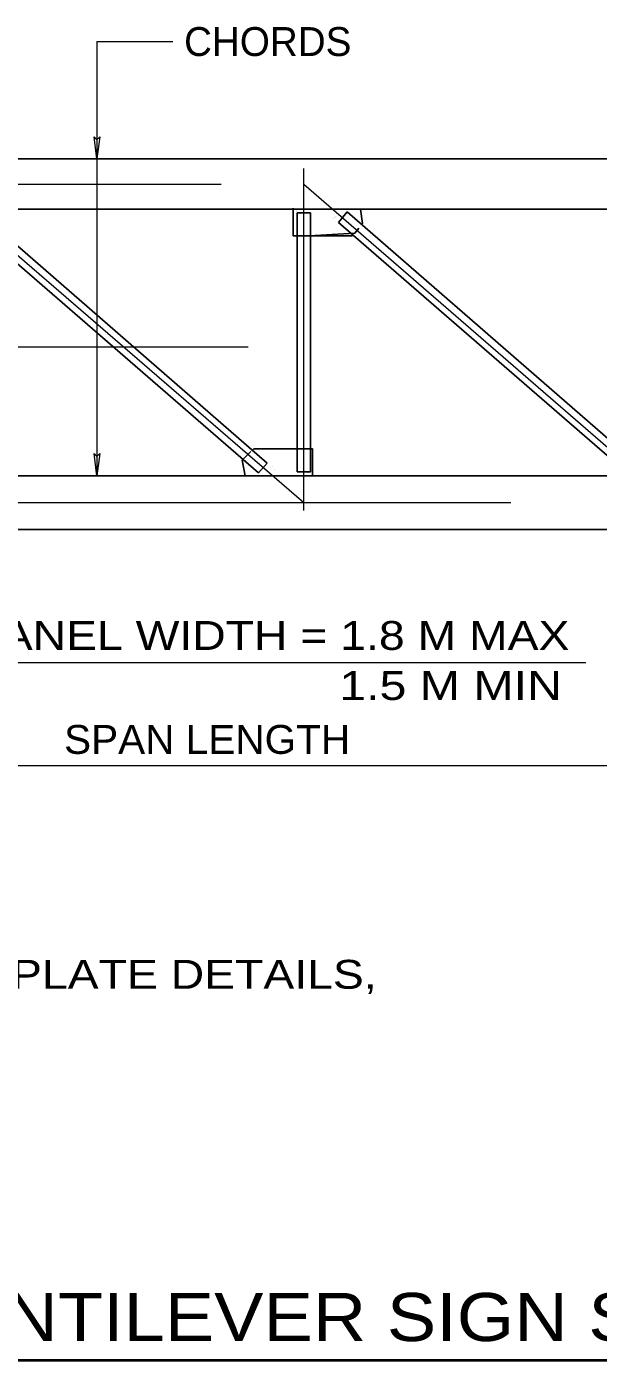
# Model space of a CAD drawing. Extents: x 312601.858 to 312602.699, y 144420.109 to 144420.704.
# Drawn here: x 312602.0731 to 312602.1325, y 144420.4937 to 144420.6322 of the extents above; entities that cross this region are included whole.
import ezdxf
from ezdxf.enums import TextEntityAlignment as Align

# ---------------------------------------------------------------- set-up
doc = ezdxf.new("R2010")
doc.units = 0
doc.header["$LTSCALE"] = 0.0012
doc.linetypes.add('DOT_DASHED', pattern=[7.7, 5, -1.2, 0.3, -1.2])
doc.layers.add('1', color=7, linetype='Continuous', lineweight=13)
doc.layers.add('2', color=7, linetype='Continuous', lineweight=25)

msp = doc.modelspace()

# ---------------------------------------------------------------- linework, layer by layer
at = {"layer": '1'}
for p, q in [((312602.0804, 144420.6307), (312602.0883, 144420.6307)), ((312602.0636, 144420.5662), (312602.1312, 144420.5662)), ((312602.0054, 144420.5555), (312602.1817, 144420.5555))]:
    msp.add_line(p, q, dxfattribs=at)
at = {"layer": '1', "lineweight": 25}
for p, q in [((312602.0222, 144420.6185), (312602.1817, 144420.6185)), ((312602.0677, 144420.6133), (312602.1012, 144420.6133)), ((312602.0682, 144420.6129), (312602.0981, 144420.5869)), ((312602.1008, 144420.6106), (312602.1008, 144420.6134)), ((312602.1008, 144420.6105), (312602.1008, 144420.6133)), ((312602.1008, 144420.6105), (312602.1008, 144420.6133)), ((312602.1008, 144420.6105), (312602.1008, 144420.6133)), ((312602.1008, 144420.6106), (312602.1008, 144420.6133)), ((312602.1012, 144420.586), (312602.1012, 144420.6129)), ((312602.1012, 144420.6129), (312602.1026, 144420.6129)), ((312602.1024, 144420.6133), (312602.1062, 144420.6133)), ((312602.1026, 144420.586), (312602.1026, 144420.6129)), ((312602.1064, 144420.613), (312602.1055, 144420.6119)), ((312602.106, 144420.6133), (312602.1394, 144420.6133)), ((312602.1064, 144420.613), (312602.1364, 144420.5869)), ((312602.0673, 144420.6118), (312602.0972, 144420.5859)), ((312602.1055, 144420.6119), (312602.1355, 144420.5859)), ((312602.108, 144420.6118), (312602.1079, 144420.6117)), ((312602.1008, 144420.6105), (312602.1012, 144420.6105)), ((312602.1008, 144420.6105), (312602.1012, 144420.6105)), ((312602.1008, 144420.6105), (312602.1012, 144420.6105)), ((312602.1069, 144420.6105), (312602.1025, 144420.6105)), ((312602.0966, 144420.5883), (312602.0967, 144420.5884)), ((312602.0967, 144420.5884), (312602.1011, 144420.5884)), ((312602.0967, 144420.5884), (312602.1011, 144420.5884)), ((312602.0967, 144420.5884), (312602.1011, 144420.5884)), ((312602.1028, 144420.5884), (312602.1024, 144420.5884)), ((312602.1028, 144420.5884), (312602.1024, 144420.5884)), ((312602.1028, 144420.5884), (312602.1024, 144420.5884)), ((312602.1028, 144420.5884), (312602.1028, 144420.5856)), ((312602.1028, 144420.5884), (312602.1028, 144420.5856)), ((312602.1028, 144420.5884), (312602.1028, 144420.5856)), ((312602.0972, 144420.5859), (312602.0981, 144420.5869)), ((312602.0643, 144420.5856), (312602.0976, 144420.5856)), ((312602.1012, 144420.5856), (312602.0974, 144420.5856)), ((312602.0988, 144420.5856), (312602.1009, 144420.5856)), ((312602.0991, 144420.5856), (312602.1012, 144420.5856)), ((312602.101, 144420.5856), (312602.0991, 144420.5856)), ((312602.1026, 144420.586), (312602.1012, 144420.586)), ((312602.1026, 144420.5856), (312602.1359, 144420.5856)), ((312602.0222, 144420.58), (312602.1817, 144420.58))]:
    msp.add_line(p, q, dxfattribs=at)
at = {"layer": '1', "linetype": 'DOT_DASHED'}
for p, q in [((312602.1019, 144420.582), (312602.1019, 144420.6175)), ((312601.9933, 144420.6159), (312602.1862, 144420.6159)), ((312602.0636, 144420.6159), (312602.1019, 144420.5828)), ((312602.1019, 144420.6159), (312602.1401, 144420.5828)), ((312601.9961, 144420.599), (312602.181, 144420.599))]:
    msp.add_line(p, q, dxfattribs=at)
at = {"layer": '1', "lineweight": 40}
msp.add_line((312601.9778, 144420.4937), (312602.169, 144420.4937), dxfattribs=at)
at = {"layer": '1'}
for points in [[(312602.0807, 144420.6208), (312602.0804, 144420.6185), (312602.0801, 144420.6208), (312602.0804, 144420.6205)], [(312602.0807, 144420.5879), (312602.0804, 144420.5856), (312602.0801, 144420.5879), (312602.0804, 144420.5876)]]:
    msp.add_lwpolyline(points, close=True, dxfattribs=at)
at = {"layer": '1', "lineweight": 25}
for points in [[(312602.1069, 144420.6105), (312602.1025, 144420.6105), (312602.1015, 144420.6105), (312602.1008, 144420.6105), (312602.1008, 144420.6133), (312602.1078, 144420.6133), (312602.108, 144420.6118)], [(312602.1076, 144420.6113), (312602.1072, 144420.6108), (312602.1025, 144420.6105)], [(312602.107, 144420.6106), (312602.1069, 144420.6105), (312602.1025, 144420.6105)], [(312602.0967, 144420.5884), (312602.1011, 144420.5884), (312602.1021, 144420.5884), (312602.1028, 144420.5884), (312602.1028, 144420.5856), (312602.0958, 144420.5856), (312602.0955, 144420.5872)], [(312602.0955, 144420.5872), (312602.0956, 144420.5873), (312602.0964, 144420.5881)]]:
    msp.add_lwpolyline(points, dxfattribs=at)
at = {"layer": '1', "linetype": 'DOT_DASHED'}
msp.add_lwpolyline([(312602.0227, 144420.5828), (312602.0234, 144420.5828), (312602.1868, 144420.5828)], dxfattribs=at)
at = {"layer": '1'}
for centre, start, end in [((312602.10185, 144420.61311), 180, 180.74184), ((312602.10185, 144420.61301), 180, 180.74184), ((312602.102225, 144420.61291), 180, 180.74184), ((312602.102225, 144420.61281), 180, 180.74184), ((312602.105448, 144420.612981), 229.1584, 229.90024), ((312602.105448, 144420.612881), 229.1584, 229.90024), ((312602.105622, 144420.61307), 229.1584, 229.90024), ((312602.105622, 144420.61297), 229.1584, 229.90024), ((312602.097978, 144420.58593), 49.1584, 49.90024), ((312602.098152, 144420.586019), 49.1584, 49.90024), ((312602.098419, 144420.585775), 49.1584, 49.90024), ((312602.101375, 144420.58609), 0, 0.74184), ((312602.101625, 144420.585895), 0, 0.74184), ((312602.10175, 144420.58589), 0, 0.74184), ((312602.101875, 144420.585895), 0, 0.74184)]:
    msp.add_arc(centre, 0.00068, start, end, dxfattribs=at)
at = {"layer": '2', "lineweight": 13}
msp.add_lwpolyline([(312602.0804, 144420.6307), (312602.0804, 144420.6185), (312602.0804, 144420.5856)], dxfattribs=at)

# ---------------------------------------------------------------- texts
at = {"layer": '2'}
msp.add_text('CHORDS', height=0.003, dxfattribs=at).set_placement((312602.09815, 144420.6292), align=Align.CENTER)
for s, height, width, p in [('PANEL WIDTH = 1.8 M MAX', 0.003, 1.2, (312602.0984, 144420.5675)), ('1.5 M MIN', 0.003, 1.25, (312602.11715, 144420.5623)), ('SPAN LENGTH', 0.003, 1.05, (312602.09185, 144420.5567)), ('FOR POST BASE PLATE DETAILS,  ', 0.003, 1.2, (312602.07175, 144420.5323)), ('ELEVATION -TYPICAL CANTILEVER SIGN SUPPORT', 0.005, 1.15, (312602.07335, 144420.4957))]:
    msp.add_text(s, height=height, dxfattribs=dict(at, width=width)).set_placement(p, align=Align.CENTER)

doc.saveas('drawing.dxf')
